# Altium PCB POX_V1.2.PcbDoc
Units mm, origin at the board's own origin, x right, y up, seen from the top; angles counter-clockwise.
Board outline 50.67 x 27 mm, 2 copper layers (Top Layer, Bottom Layer); 28 components, 26 nets, 115 pads, 65 vias.
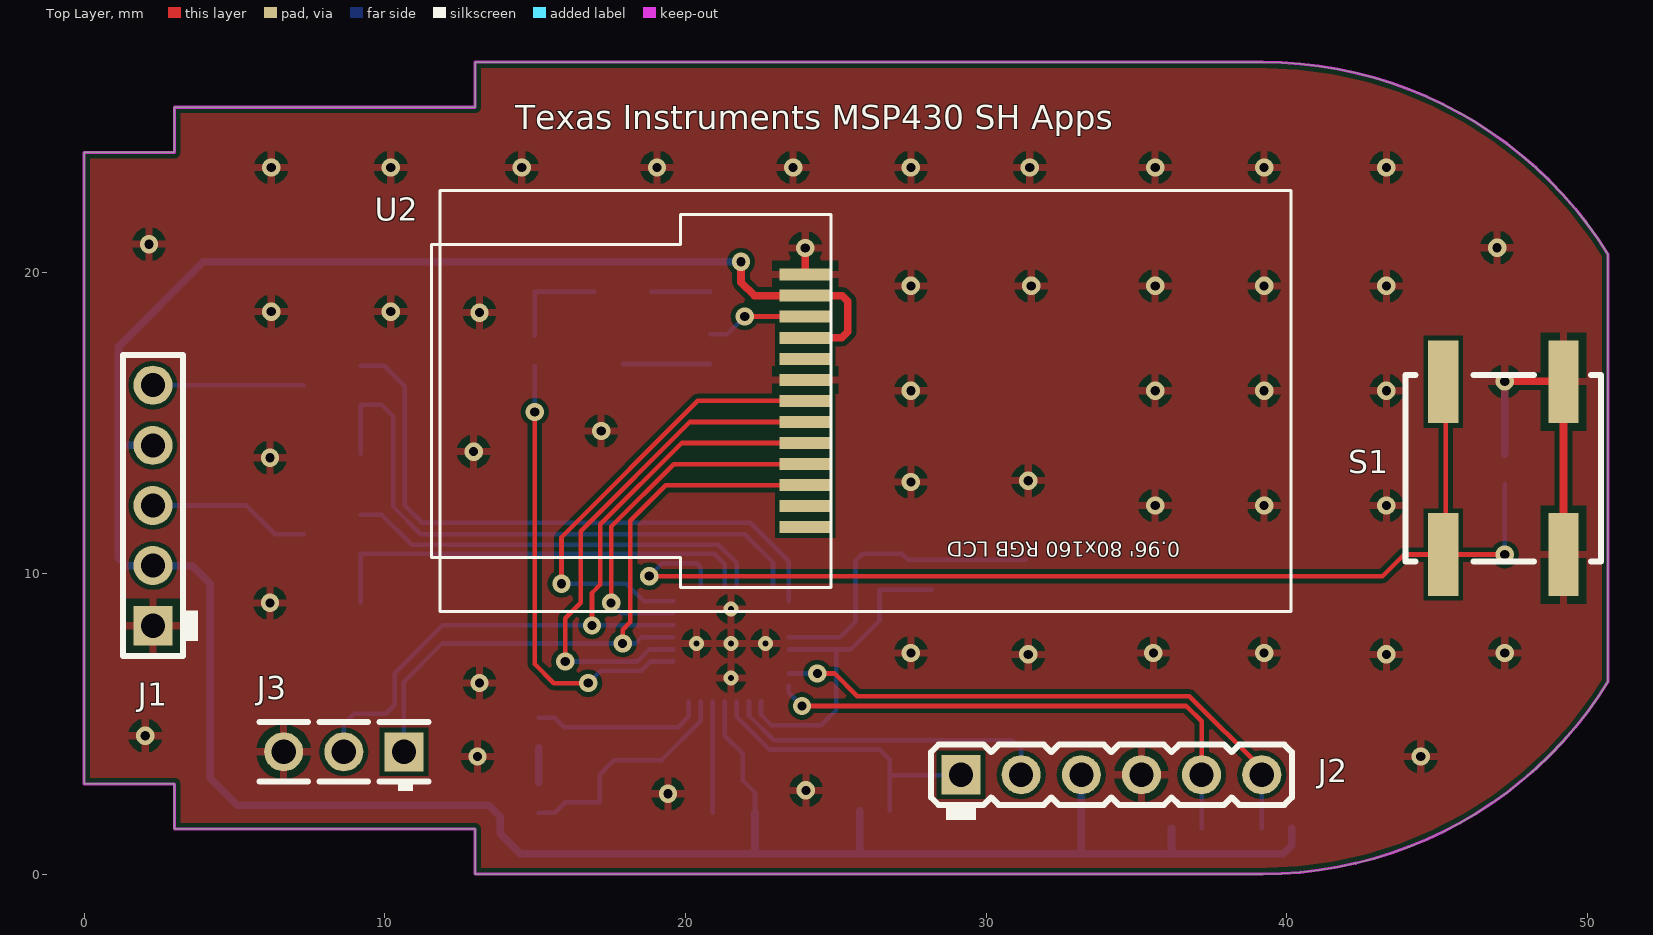
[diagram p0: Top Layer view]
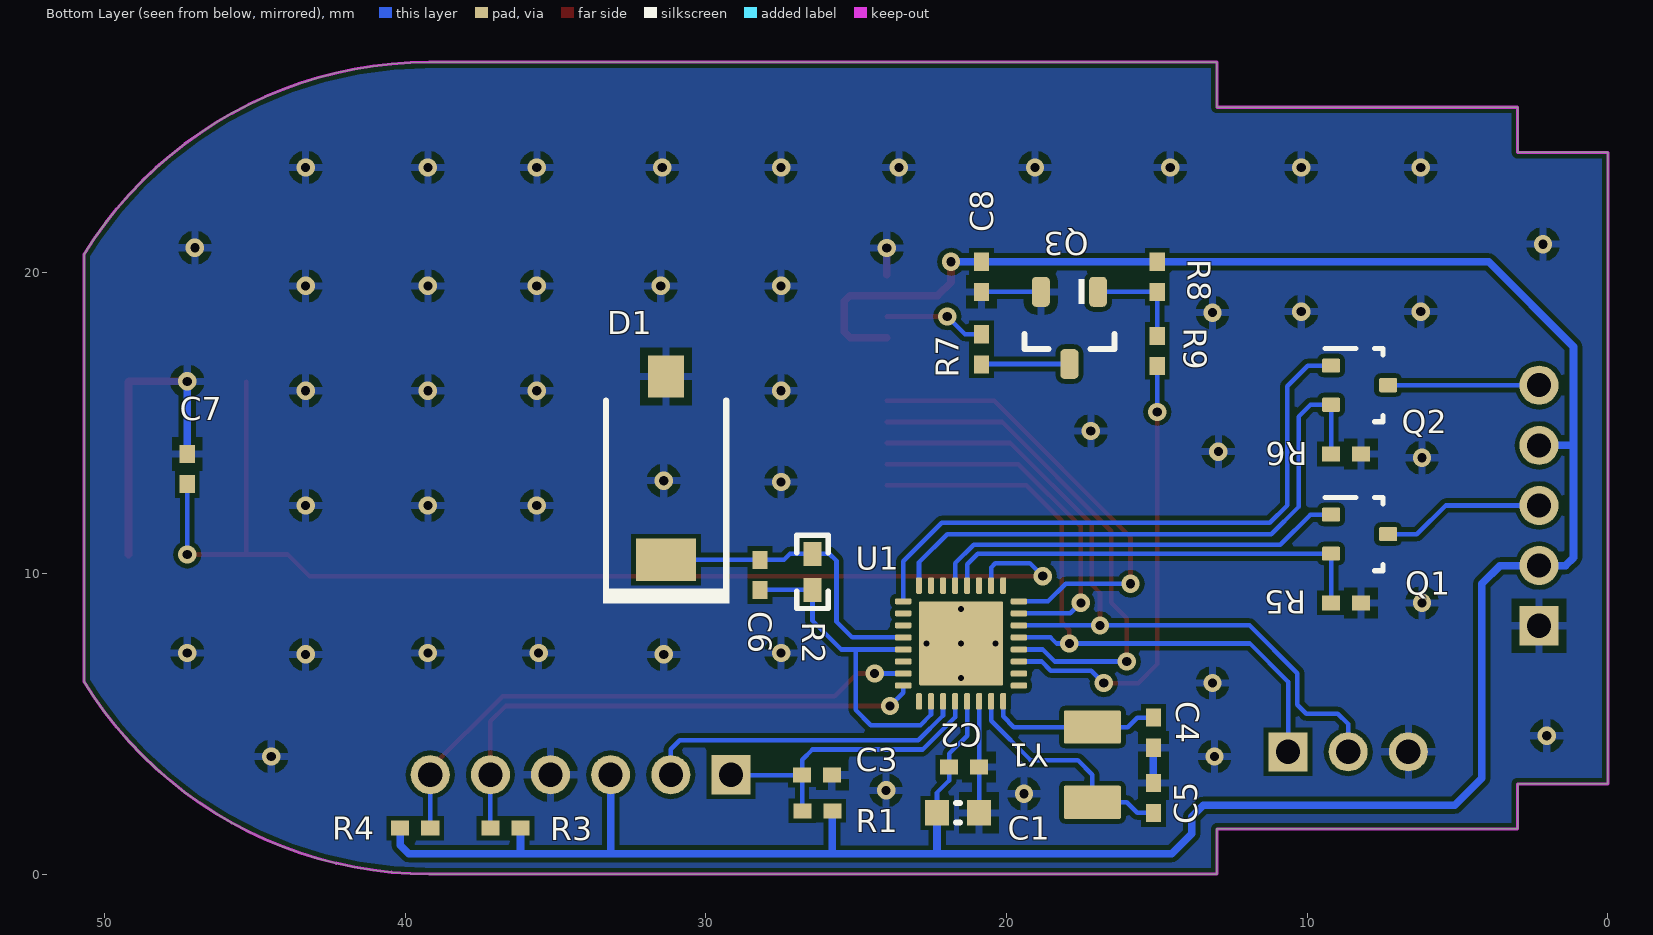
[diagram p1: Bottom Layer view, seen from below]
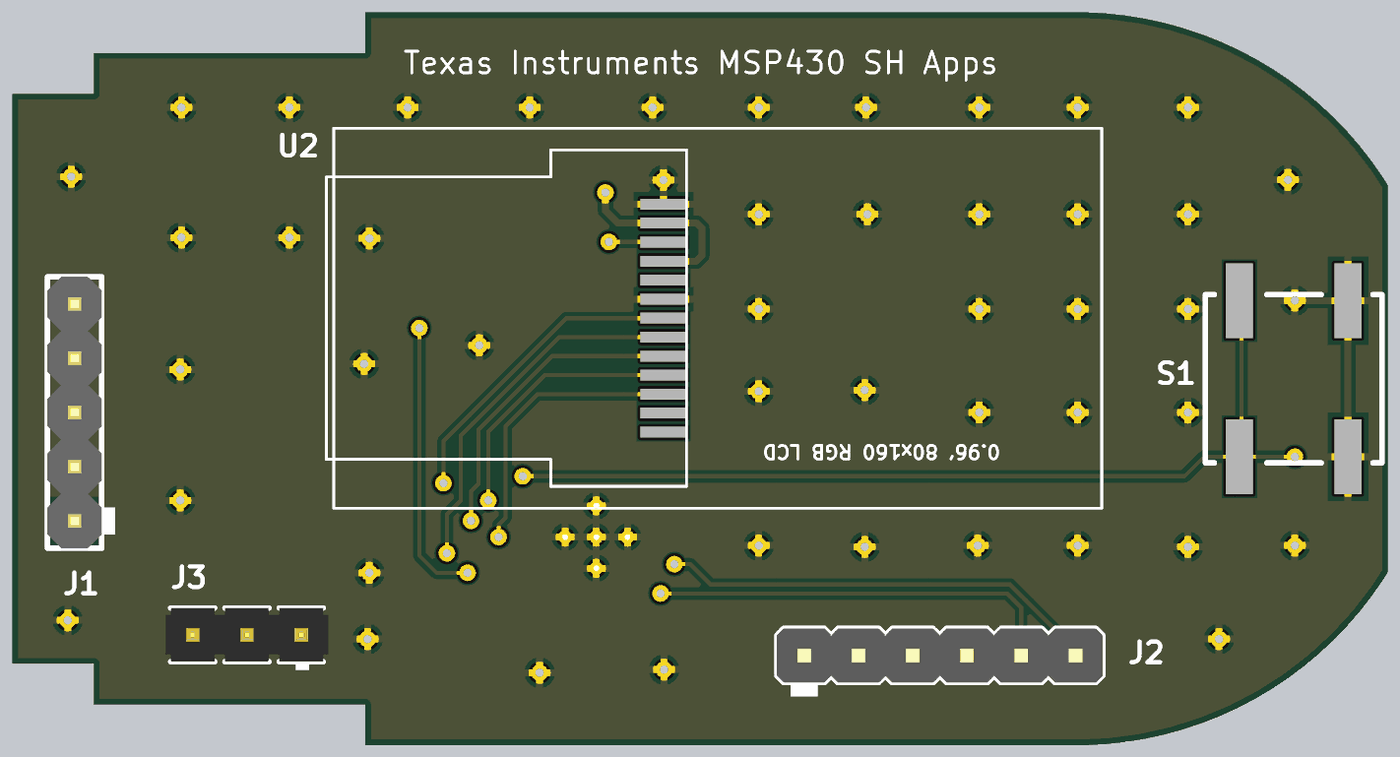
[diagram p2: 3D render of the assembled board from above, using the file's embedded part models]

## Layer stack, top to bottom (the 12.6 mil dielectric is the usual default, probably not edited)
Top Solder: solder mask 0.0102, Solder Resist, Dk 3.5
Top Layer: signal copper 0.0356
Dielectric 1: dielectric 0.32, FR-4, Dk 4.8
Bottom Layer: signal copper 0.0356
Bottom Solder: solder mask 0.0102, Solder Resist, Dk 3.5

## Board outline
3,1.5 3,3 0,3 0,24 3,24 3,25.5 13,25.5 13,27 39.2,27 cw(c39.2,13.5) 50.674,20.614 50.673,20.614 50.673,6.386 50.674,6.386 cw(c39.2,13.5) 39.2,0 13,0 13,1.5

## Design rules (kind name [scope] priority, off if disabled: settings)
Clearance [All] p1: gap=0.152 ignorepadtopadclearanceinfootprint=TRUE except(0: Arc-Hole Track-Hole SMDPad-Hole THPad-Hole Via-Hole Fill-Hole Poly-Hole Region-Hole Text-Hole)
MinimumSolderMaskSliver [All] p1 off: minsoldermaskwidth=0.152
PolygonConnect [All] p1: connectstyle=Relief reliefconductorwidth=0.254 reliefentries=4 polygonreliefangle="90 Angle" airgapwidth=0.254
RoutingVias [All] p1: holewidth=0.305 width=0.61 viastyle="Through Hole" minholewidth=0.305 minwidth=0.61 maxholewidth=0.711 maxwidth=1.27
SilkToSolderMaskClearance [IsPad] p1: minsilkscreentomaskgap=0.102 clearancetoexposedcopper=TRUE
SolderMaskExpansion [All] p1: expansion=0.102
Width [All] p1: maxlimit=0.381 minlimit=0.152 preferedwidth=0.203 minimp=50.000000 maximp=50.000000 favimp=50.000000
28 further rules are at their usual default settings.

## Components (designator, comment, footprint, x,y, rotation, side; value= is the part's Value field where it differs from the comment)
C1 "GRM188R60J106ME84" 0603L 21.61,2.032 r180 bottom value=10uF
C2 "GRM155R61A104KA01D" 0402L 21.41,3.556 r0 bottom value=0.1uF
C3 "C1005NP01H102J050BA" 0402L 26.297,3.286 r180 bottom value=1000pF
C4 "GRM1555C1E120JA01D" 0402L 15.113,4.699 r270 bottom value=12pF
C5 "GRM1555C1E120JA01D" 0402L 15.113,2.532 r90 bottom value=12pF
C6 "GRM1555C1H1R0CA01D" 0402L 28.194,9.948 r90 bottom value=1pF
C7 "GRM155R61A104KA01D" 0402L 47.244,13.47 r90 bottom value=0.1uF
C8 "GRM155R61A105KE15D" 0402L 20.828,19.861 r90 bottom value=1uF
D1 "BPW 34 SR" BPW34SR 31.319,13.5 r270 bottom locked
J1 "951105-8622-AR" 3M_951105-8622-AR 2.286,12.256 r90 top
J2 "M22-2510605" Harwin_M22-25106 34.163,3.302 r0 top
J3 "PTT-103-01-L-S" Samtec_PTT-103-01-x-S 8.636,4.064 r180 top
Q1 "BSS138W-7-F" SOT-323 8.255,11.303 r180 bottom value=50V
Q2 "BSS138W-7-F" SOT-323 8.255,16.256 r180 bottom value=50V
Q3 "BC849CLT1G" SOT-23 17.907,18.161 r270 bottom value="30 V"
R1 "CRCW040247K0JNED" 0402L 26.289,2.101 r180 bottom value=47k
R2 "CRCW04021M00FKED" 0402 26.452,10.048 r270 bottom value=1.00Meg
R3 "CRCW04022K20JNED" 0402L 36.663,1.524 r180 bottom value=2.2k
R4 "CRCW04022K20JNED" 0402L 39.663,1.524 r0 bottom value=2.2k
R5 "504L50R0FTNCFT" 0402L 8.705,9.017 r0 bottom value=50
R6 "504L50R0FTNCFT" 0402L 8.705,13.97 r0 bottom value=50
R7 "CRCW040210R0JNED" 0402L 20.828,17.45 r90 bottom value=10
R8 "CRCW040210K0JNED" 0402L 14.986,19.861 r90 bottom value=10k
R9 "CRCW04021K00JNED" 0402L 14.986,17.399 r90 bottom value=1.0k
S1 "B3SL-1002P" SW_B3SL-1002P 47.2,13.5 r90 top
U1 "MSP430FR2355RSM" RSM0032B 21.51,7.667 r90 bottom
U2 "0.96 inch LCD RGB display" GMT096-01 40.132,22.733 r180 top
Y1 "ECS-.327-12.5-34B-TR" ECS_ECX_31B 17.145,3.636 r90 bottom

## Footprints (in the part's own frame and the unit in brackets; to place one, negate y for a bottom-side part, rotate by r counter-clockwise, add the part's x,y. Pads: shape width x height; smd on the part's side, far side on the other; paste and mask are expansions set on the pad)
3M_951105-8622-AR [mm] "Header, 2mm, 5x1, TH"
  rect 1.3x1.3 hole 0.8: 1(-4,0)
  round 1.3 hole 0.8: 2(-2,0) 3(0,0) 4(2,0) 5(4,0)
  silkscreen extent -5,-1.5 5,1, body extent -5,-1 5,1, height 5.9
0402 [mm] "0402 from SM-752 data"
  rect 0.8x0.6 smd: 1(-0.6,0) 2(0.6,0)
  silkscreen extent -1.22,-0.52 1.22,0.52, body extent -0.55,-0.3 0.55,0.3, height 0.6
0402L [mm] "0402 from SM-752 data"
  rect 0.6x0.5 smd: 1(-0.5,0) 2(0.5,0)
  body extent -0.55,-0.3 0.55,0.3, height 0.6
0603L [mm] "0603 from SM-752 data"
  rect 0.8x0.85 smd: 1(-0.7,0) 2(0.7,0)
  silkscreen extent -0.07,-0.33 0.07,0.33, body extent -0.87,-0.47 0.87,0.47, height 1
BPW34SR [mm] "SMD, 2-Leads, Body 3.85x4.4mm"
  rect 1.4x1.2 smd paste-0.05 mask+0.05: 1(-3.05,0)
  rect 1.4x2 smd paste-0.05 mask+0.05: 2(3.05,0)
  silkscreen extent -2.25,-2.1 4.5,2.1, body extent -2.25,-2 2.25,2, height 1.2
ECS_ECX_31B [mm] "SMD, 2-Leads, Body 3.2x1.5mm"
  rrect9% 1.1x1.9 smd: 1(-1.25,0) 2(1.25,0)
  body extent -1.6,-0.75 1.6,0.75, height 0.9
GMT096-01 [mm]
  rect 1.7x0.4 smd: 1(16.15,11.2) 2(16.15,10.5) 3(16.15,9.8) 4(16.15,9.1) 5(16.15,8.4) 6(16.15,7.7) 7(16.15,7) 8(16.15,6.3) 9(16.15,5.6) 10(16.15,4.9) 11(16.15,4.2) 12(16.15,3.5) 13(16.15,2.8)
  silkscreen extent 0,0 28.57,14
Harwin_M22-25106 [mm] "Header, 2mm, 6x1, TH"
  rect 1.3x1.3 hole 0.8: 1(-5,0)
  round 1.3 hole 0.8: 2(-3,0) 3(-1,0) 4(1,0) 5(3,0) 6(5,0)
  silkscreen extent -6,-1.5 6,1, body extent -6,-1 6,1, height 5
RSM0032B [mm] "QFN, 32-Leads, Body 4x4mm, Pitch 0.4mm, Thermal Pad 2.8x2.8mm, TI Recommended"
  rrect50% 0.55x0.2 smd: 1(-1.925,1.4) 2(-1.925,1) 3(-1.925,0.6) 4(-1.925,0.2) 5(-1.925,-0.2) 6(-1.925,-0.6) 7(-1.925,-1) 8(-1.925,-1.4) 17(1.925,-1.4) 18(1.925,-1) 19(1.925,-0.6) 20(1.925,-0.2) 21(1.925,0.2) 22(1.925,0.6) 23(1.925,1) 24(1.925,1.4)
  rrect50% 0.2x0.55 smd: 9(-1.4,-1.925) 10(-1,-1.925) 11(-0.6,-1.925) 12(-0.2,-1.925) 13(0.2,-1.925) 14(0.6,-1.925) 15(1,-1.925) 16(1.4,-1.925) 25(1.4,1.925) 26(1,1.925) 27(0.6,1.925) 28(0.2,1.925) 29(-0.2,1.925) 30(-0.6,1.925) 31(-1,1.925) 32(-1.4,1.925)
  rrect8% 1.23x1.23 on Bottom Paste: 33(-0.715,-0.715) 33(-0.715,0.715) 33(0.715,-0.715) 33(0.715,0.715)
  rrect4% 2.8x2.8 smd paste-1.4: 33(0,0)
  body extent -2,-2 2,2, height 1.01
Samtec_PTT-103-01-x-S [mm] "Header, 2mm, 3x1, TH"
  rect 1.3x1.3 hole 0.81: 1(-2,0)
  round 1.3 hole 0.81: 2(0,0) 3(2,0)
  silkscreen extent -2.81,-0.99 2.81,1.3, body extent -3,-0.99 3,0.99, height 4.7
SOT-23 [mm] "SOT23, 3-Leads, Body 2.9x1.3mm, Pitch 0.95mm, Lead Span 2.5mm, IPC Medium Density"
  rrect50% 1x0.6 smd: 1(-1.2,0.95) 2(-1.2,-0.95) 3(1.2,0)
  silkscreen extent -1.62,-1.5 0.7,1.5, body extent -1.16,-1.45 1.21,1.45, height 1
SOT-323 [mm] "Diodes Inc recommended land pattern.  2016-02-24"
  rrect21% 0.6x0.47 smd: 1(-0.95,0.65) 2(-0.95,-0.65) 3(0.95,0)
  silkscreen extent -1.14,-1.22 0.78,1.22, body extent -1.13,-1.13 1.12,1.12, height 1.13
SW_B3SL-1002P [mm] "Omron"
  rect 2.75x1 smd: 1(-2.875,2) 2(2.875,2) 3(-2.875,-2) 4(2.875,-2)
  silkscreen extent -3.1,-3.25 3.1,3.25, body extent -3.2,-3.35 3.2,3.35, height 3.4

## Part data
C1: library part CMP-0007304-5, "CAP, CERM, 10 uF, 6.3 V, +/- 20%, X5R, 0603", Cap_Case=0603, Manufacturer=MuRata, Supplier Part Number 1=490-7316-1-ND, TempCo=X5R, Tolerance_%=20%, Value1=Unknown, Value2=6.3V, ValueDisplayed=10uF
C2 C7: library part CMP-0006562-2, "CAP, CERM, 0.1 uF, 10 V, +/- 10%, X5R, 0402", Cap_Case=0402, Manufacturer=MuRata, Supplier Part Number 1=490-1318-1-ND, TempCo=X5R, Tolerance_%=10%, Value1=Unknown, Value2=10V, ValueDisplayed=0.1uF
C3: library part CMP-0006254-2, "CAP, CERM, 1000 pF, 50 V, +/- 5%, C0G/NP0, 0402", Cap_Case=0402, Manufacturer=TDK, Supplier Part Number 1=445-13785-1-ND, TempCo=C0G/NP0, Tolerance_%=5%, Value1=Unknown, Value2=50V, ValueDisplayed=1000pF
C4 C5: library part CMP-0006375-2, "CAP, CERM, 12 pF, 25 V, +/- 5%, C0G/NP0, 0402", Cap_Case=0402, Manufacturer=MuRata, Supplier Part Number 1=81-GRM1555C1E120JA1D, TempCo=C0G/NP0, Tolerance_%=5%, Value1=Unknown, Value2=25V, ValueDisplayed=12pF
C6: library part CMP-0006427-2, "CAP, CERM, 1 pF, 50 V, +/- 5%, C0G/NP0, 0402", Cap_Case=0402, Manufacturer=MuRata, Supplier Part Number 1=490-3199-1-ND, TempCo=C0G/NP0, Tolerance_%=5%, Value1=Unknown, Value2=50V, ValueDisplayed=3pF
C8: library part CMP-0006563-2, "CAP, CERM, 1 uF, 10 V, +/- 10%, X5R, 0402", Cap_Case=0402, Manufacturer=MuRata, Supplier Part Number 1=490-3890-1-ND, TempCo=X5R, Tolerance_%=10%, Value1=Unknown, Value2=10V, ValueDisplayed=1uF
D1: library part CMP-0005335-2, "PIN Photodiode, SMD", Manufacturer=OSRAM, Supplier Part Number 1=751-1501-1-ND
J1: library part CMP-0075215-1, "Header, 2mm, 5x1, Gold, Black, TH", Color=Black, Current_A=1A, Manufacturer=3M, Supplier Part Number 1=3M9324-ND, Voltage_V=1kV
J2: library part CMP-0075299-1, "Header, 2mm, 6x1, Gold, TH", Color=Black, Current_A=1A, Manufacturer=Harwin, Supplier Part Number 1=952-1315-ND, Voltage_V=500V
J3: library part CMP-0055571-1, "Header, 2mm, 3x1, Gold, TH", Color=Black, Current_A=2.9A, Manufacturer=Samtec
Q1 Q2: library part CMP-0000757-1, "MOSFET, N-CH, 50 V, 0.2 A, SOT-323", Alternate Manufacturer=None, Manufacturer="Diodes Inc.", Supplier Part Number 1=BSS138W-FDICT-ND, Value1=3
Q3: library part CMP-0000378-2, "Transistor, NPN, 30 V, 0.1 A, SOT-23", Manufacturer="ON Semiconductor", Supplier Part Number 1=BC849CLT1GOSCT-ND, Value1="0.1 A", Value2=800
R1: library part CMP-0026935-3, "RES, 47 k, 5%, 0.063 W, AEC-Q200 Grade 0, 0402", Manufacturer=Vishay-Dale, Power_W=63mW, Supplier Part Number 1=541-47KJCT-ND, TempCo="200 ppm/C", Tolerance_%=5%, Value2=0.063W, Value_Code=47k0, ValueDisplayed=47k
R2: library part CMP-0026100-2, "RES, 1.00 M, 1%, 0.063 W, AEC-Q200 Grade 0, 0402", Manufacturer=Vishay-Dale, Power_W=63mW, Supplier Part Number 1=541-1.00MLCT-ND, TempCo="100 ppm/C", Tolerance_%=1%, Value2=0.063W, Value_Code=1M00, ValueDisplayed=1.00M
R3 R4: library part CMP-0026890-5, "RES, 2.2 k, 5%, 0.063 W, AEC-Q200 Grade 0, 0402", Manufacturer=Vishay-Dale, Power_W=63mW, Supplier Part Number 1=541-2.2KJCT-ND, TempCo="200 ppm/C", Tolerance_%=5%, Value2=0.063W, Value_Code=2k20, ValueDisplayed=2.2k
R5: library part CMP-0025948-2, "RES, 20, 1%, 0.125 W, AEC-Q200 Grade 1, 0402", Manufacturer="AT Ceramics", Power_W=125mW, Supplier Part Number 1=1284-1326-1-ND, TempCo="150 ppm/C", Tolerance_%=1%, Value2=0.125W, Value_Code=50R0, ValueDisplayed=20
R6: library part CMP-0025948-2, "RES, 50, 1%, 0.125 W, AEC-Q200 Grade 1, 0402", Manufacturer="AT Ceramics", Power_W=125mW, Supplier Part Number 1=1284-1326-1-ND, TempCo="150 ppm/C", Tolerance_%=1%, Value2=0.125W, Value_Code=50R0, ValueDisplayed=20
R7: library part CMP-0026827-3, "RES, 10, 5%, 0.063 W, AEC-Q200 Grade 0, 0402", Manufacturer=Vishay-Dale, Power_W=63mW, Supplier Part Number 1=541-10JCT-ND, TempCo="200 ppm/C", Tolerance_%=5%, Value2=0.063W, Value_Code=10R0, ValueDisplayed=10
R8: library part CMP-0026825-5, "RES, 10 k, 5%, 0.063 W, AEC-Q200 Grade 0, 0402", Manufacturer=Vishay-Dale, Power_W=63mW, Supplier Part Number 1=541-10KJCT-ND, TempCo="200 ppm/C", Tolerance_%=5%, Value2=0.063W, Value_Code=10k0, ValueDisplayed=10k
R9: library part CMP-0026852-3, "RES, 1.0 k, 5%, 0.063 W, AEC-Q200 Grade 0, 0402", Manufacturer=Vishay-Dale, Power_W=63mW, Supplier Part Number 1=541-1.0KJCT-ND, TempCo="200 ppm/C", Tolerance_%=5%, Value2=0.063W, Value_Code=1k00, ValueDisplayed=1.0k
S1: library part CMP-0002310-1, "SWITCH TACTILE SPST-NO 0.05A 12V", CurrentRating_mA=50A, Manufacturer="Omron Electronic Components", Supplier Part Number 1=SW1064CT-ND
U1: library part CMP-0860022-1, "MSP430FR235x mixed-signal microcontrollers, RSM0032B (VQFN-32)", Alternate Manufacturer="Texas Instruments"
U2: library part GMT096-01
Y1: library part CMP-0078856-1, "Crystal, 32.768 KHz, 20 ppm, SMD", Frequency_Fixed=32.768kHz, Frequency Tolerance="20 ppm", Manufacturer="ECS Inc.", Supplier Part Number 1=XC1617CT-ND

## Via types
v1: diameter 0.61, hole 0.305, Top Layer to Bottom Layer, 60 vias
v2: diameter 0.5, hole 0.2, Top Layer to Bottom Layer, 5 vias

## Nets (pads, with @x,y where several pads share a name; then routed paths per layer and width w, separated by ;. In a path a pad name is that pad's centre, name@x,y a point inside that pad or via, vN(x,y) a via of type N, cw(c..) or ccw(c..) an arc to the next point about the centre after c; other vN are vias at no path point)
GND: C1.2 C2.1 C3.2 C4.2 C5.2 C7.2 C8.1 D1.1 J1.1 J2.4 J3.3 Q3.2 R5.1 R6.1 S1.3 S1.4 U1.6 U1.33@21.51,7.667 U2.8 U2.13 | length 17.9
  Top Layer w0.254: U2.13 v1(23.982,20.819) ; v1(47.244,16.383) 49.192,16.383 S1.4 S1.3
  Bottom Layer w0.152: Q3.2 C8.1 ; C1.2 C2.1 U1.6
  Bottom Layer w0.254: C5.2 C4.2 ; C7.2 v1(47.244,16.383)
  other v1: 19.419,2.667 24.003,2.782 13.081,3.907 44.45,3.907 2.032,4.598 13.147,6.35 31.396,7.304 43.307,7.304 27.495,7.352 35.56,7.352 39.243,7.352 47.244,7.352 6.18,9.017 35.619,12.257 39.243,12.256 43.307,12.256 27.495,13.038 31.396,13.081 6.18,13.843 12.954,14.047 17.195,14.732 27.495,16.07 35.619,16.07 39.243,16.07 43.307,16.07 13.147,18.669 6.223,18.703 10.198,18.703 27.495,19.558 31.496,19.558 35.619,19.558 39.243,19.558 43.307,19.558 46.99,20.828 2.159,20.946 6.223,23.495 10.198,23.495 14.555,23.495 19.054,23.495 23.579,23.495 27.495,23.495 31.446,23.495 35.619,23.495 39.243,23.495 43.307,23.495
  other v2: 21.51,6.517 20.36,7.667 21.51,7.667 22.66,7.667 21.51,8.817
I2C_SCL: J2.6 R4.1 U1.31 | length 19
  Top Layer w0.152: v1(24.384,6.667) 24.965,6.667 25.715,5.918 36.756,5.918 39.163,3.511 J2.6
  Bottom Layer w0.152: U1.31 v1(24.384,6.667) ; R4.1 J2.6
I2C_SDA: J2.5 R3.1 U1.32 | length 17.9
  Top Layer w0.152: v1(23.876,5.588) 36.655,5.588 37.163,5.08 J2.5
  Bottom Layer w0.152: U1.32 23.435,6.029 v1(23.876,5.588) ; R3.1 J2.5
IR_LED: J1.5 Q2.3 | length 5
  Bottom Layer w0.152: J1.5 Q2.3
LCD_BLK: R9.1 U1.11 | length 15.1
  Top Layer w0.152: v1(14.986,15.367) 14.986,6.985 15.621,6.35 v1(16.764,6.35)
  Bottom Layer w0.152: v1(14.986,15.367) R9.1 ; v1(16.764,6.35) 17.176,6.762 18.522,6.762 18.827,7.067 U1.11
LCD_CS: U1.16 U2.7 | length 15.5
  Top Layer w0.152: v1(15.875,9.652) 15.875,11.199 20.409,15.733 U2.7
  Bottom Layer w0.152: v1(15.875,9.652) 18.034,9.652 18.619,9.067 U1.16
LCD_DC: J3.2 U1.14 U2.5 | length 25.3
  Top Layer w0.152: v1(16.891,8.267) 16.891,9.347 17.17,9.627 17.17,11.632 19.871,14.333 U2.5
  Bottom Layer w0.152: J3.2 8.636,4.989 8.981,5.334 10.033,5.334 10.331,5.632 10.331,6.679 11.919,8.267 v1(16.891,8.267) U1.14
LCD_RES: U1.12 U2.6 | length 17.3
  Top Layer w0.152: v1(16.002,7.067) 16.002,8.509 16.51,9.017 16.51,11.403 20.14,15.033 U2.6
  Bottom Layer w0.152: v1(16.002,7.067) 18.396,7.067 18.796,7.467 U1.12
LCD_SCL: U1.15 U2.4 | length 12.1
  Top Layer w0.152: v1(17.526,9.017) 17.526,11.557 19.602,13.633 U2.4
  Bottom Layer w0.152: v1(17.526,9.017) 17.876,8.667 U1.15
LCD_SDA: J3.1 U1.13 U2.3 | length 22.4
  Top Layer w0.152: v1(17.907,7.667) 17.907,8.128 18.161,8.382 18.161,11.749 19.345,12.933 U2.3
  Bottom Layer w0.152: J3.1 10.636,6.4 11.903,7.667 v1(17.907,7.667) 18.335,7.667 18.535,7.867 U1.13
LEDK: R7.2 U2.11 | length 3.4
  Top Layer w0.152: v1(21.971,18.542) 23.973,18.542 U2.11
  Bottom Layer w0.152: R7.2 21.379,17.95 v1(21.971,18.542)
NetQ3_1: Q3.1 R8.1 R9.2 | length 3.4
  Bottom Layer w0.152: R9.2 R8.1 Q3.1
NetQ3_3: Q3.3 R7.1 | length 2.9
  Bottom Layer w0.152: Q3.3 20.817,16.961 R7.1
OA1-: Q1.2 R5.2 U1.20 | length 14.6
  Bottom Layer w0.152: R5.2 Q1.2 9.21,10.648 20.96,10.648 21.31,10.298 U1.20
OA1O: Q1.1 U1.21 | length 13.9
  Bottom Layer w0.152: Q1.1 9.891,11.953 10.891,10.953 21.086,10.953 21.71,10.329 U1.21
OA2-: C6.2 D1.2 R2.1 U1.28 | length 10.3
  Bottom Layer w0.152: U1.28 25.127,7.867 25.654,8.394 25.654,10.414 25.888,10.648 R2.1 27.198,10.648 27.398,10.448 C6.2 28.196,10.45 D1.2
OA2O: C6.1 R2.2 U1.2 U1.29 | length 11.5
  Bottom Layer w0.152: U1.2 22.51,5.303 22.86,4.953 24.511,4.953 25.019,5.461 25.019,7.467 ; U1.29 25.019,7.467 ; C6.1 R2.2 26.452,8.418 25.501,7.467 25.019,7.467
OA3-: Q2.2 R6.2 U1.24 | length 20
  Bottom Layer w0.152: R6.2 Q2.2 9.89,15.606 10.287,15.209 10.287,12.207 11.191,11.303 21.971,11.303 22.91,10.364 U1.24
OA3O: Q2.1 U1.25 | length 20.6
  Bottom Layer w0.152: Q2.1 9.987,16.906 10.668,16.225 10.668,12.257 11.241,11.684 22.148,11.684 23.435,10.397 U1.25
RED_LED: J1.3 Q1.3 | length 5.4
  Bottom Layer w0.152: J1.3 5.397,12.256 6.35,11.303 Q1.3
RST/SBWTDIO: C3.1 J2.1 R1.1 U1.4 | length 10.3
  Bottom Layer w0.152: U1.4 21.71,5.214 22.784,4.14 26.451,4.14 26.797,3.794 C3.1 ; R1.1 26.789,3.278 C3.1 ; J2.1 29.147,3.286 C3.1
TEST/SBWTCK: J2.2 U1.3 | length 10.8
  Bottom Layer w0.152: U1.3 22.11,5.272 22.937,4.445 30.861,4.445 31.163,4.143 J2.2
VBAT: C1.1 C2.2 C8.2 J1.2 J1.4 J2.3 R1.2 R3.2 R4.2 R8.2 U1.5 U2.10 U2.12 | length 95.3
  Top Layer w0.254: v1(21.844,20.361) 21.844,19.685 22.296,19.233 U2.12 25.217,19.233 25.4,19.05 25.4,18.034 25.199,17.833 U2.10
  Bottom Layer w0.152: U1.5 21.31,4.598 21.91,3.998 C2.2 21.91,3.109 22.31,2.709 C1.1
  Bottom Layer w0.254: J1.4 1.143,14.256 ; v1(21.844,20.361) C8.2 R8.2 3.967,20.361 1.143,17.537 1.143,14.256 ; C1.1 22.31,0.677 ; R1.2 25.789,0.685 25.781,0.677 ; J2.3 33.163,0.693 33.147,0.677 ; R3.2 36.163,0.677 ; R4.2 40.163,0.962 39.878,0.677 36.163,0.677 ; 1.143,14.256 1.143,10.524 1.411,10.256 J1.2 3.587,10.256 4.191,9.652 4.191,3.186 5.091,2.286 13.462,2.286 13.843,1.905 13.843,1.342 14.508,0.677 22.31,0.677 ; 22.31,0.677 25.781,0.677 ; 25.781,0.677 33.147,0.677 ; 33.147,0.677 36.163,0.677
WAKE_BTN: C7.1 S1.1 S1.2 U1.18 | length 39.4
  Top Layer w0.152: v1(18.796,9.906) 43.18,9.906 43.899,10.625 S1.1 S1.1@45.276,10.625 ; S1.2@45.276,16.375 S1.1@45.276,10.625 ; v1(47.244,10.625) S1.1@45.276,10.625
  Bottom Layer w0.152: v1(18.796,9.906) 19.219,10.329 20.374,10.329 20.51,10.193 U1.18 ; v1(47.244,10.625) C7.1
XIN: C5.1 U1.7 Y1.1 | length 7.8
  Bottom Layer w0.152: C5.1 15.648,2.032 16.002,2.386 Y1.1 17.145,3.302 17.633,3.79 19.201,3.79 20.51,5.099 U1.7
XOUT: C4.1 U1.8 Y1.2 | length 5.8
  Bottom Layer w0.152: C4.1 15.648,5.199 15.961,4.886 Y1.2 19.753,4.886 20.11,5.243 U1.8
pads on no net: U1.1 U1.9 U1.10 U1.17 U1.19 U1.22 U1.23 U1.26 U1.27 U1.30 U1.33@20.795,6.952 U1.33@20.795,8.382 U1.33@22.225,6.952 U1.33@22.225,8.382 U2.1 U2.2 U2.9

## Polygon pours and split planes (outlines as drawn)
GND on Bottom Layer (solid, remove dead copper, pour order 2): 0,3 3,3 3,1.5 13,1.5 13,0 50.674,0 50.673,0.001 50.673,27 13,27 13,25.5 3,25.5 3,24 0,24
GND on Top Layer (solid, remove dead copper, pour order 4): 0,0 50.673,0 50.673,11.938 50.8,12.065 50.8,27 0,27

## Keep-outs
Keep-Out Layer:
  the board outline again, w0.102

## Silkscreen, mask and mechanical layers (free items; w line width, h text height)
Top Overlay:
  text "Texas Instruments MSP430 SH Apps" at 14.337,24.765 h0.8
